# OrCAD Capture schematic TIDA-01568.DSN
size B; title: TIDA-01568 Power Sequence Simulation; rev: 1.0; note: TI Design: TIDA-01568; note: Synchronous Step Down Converter
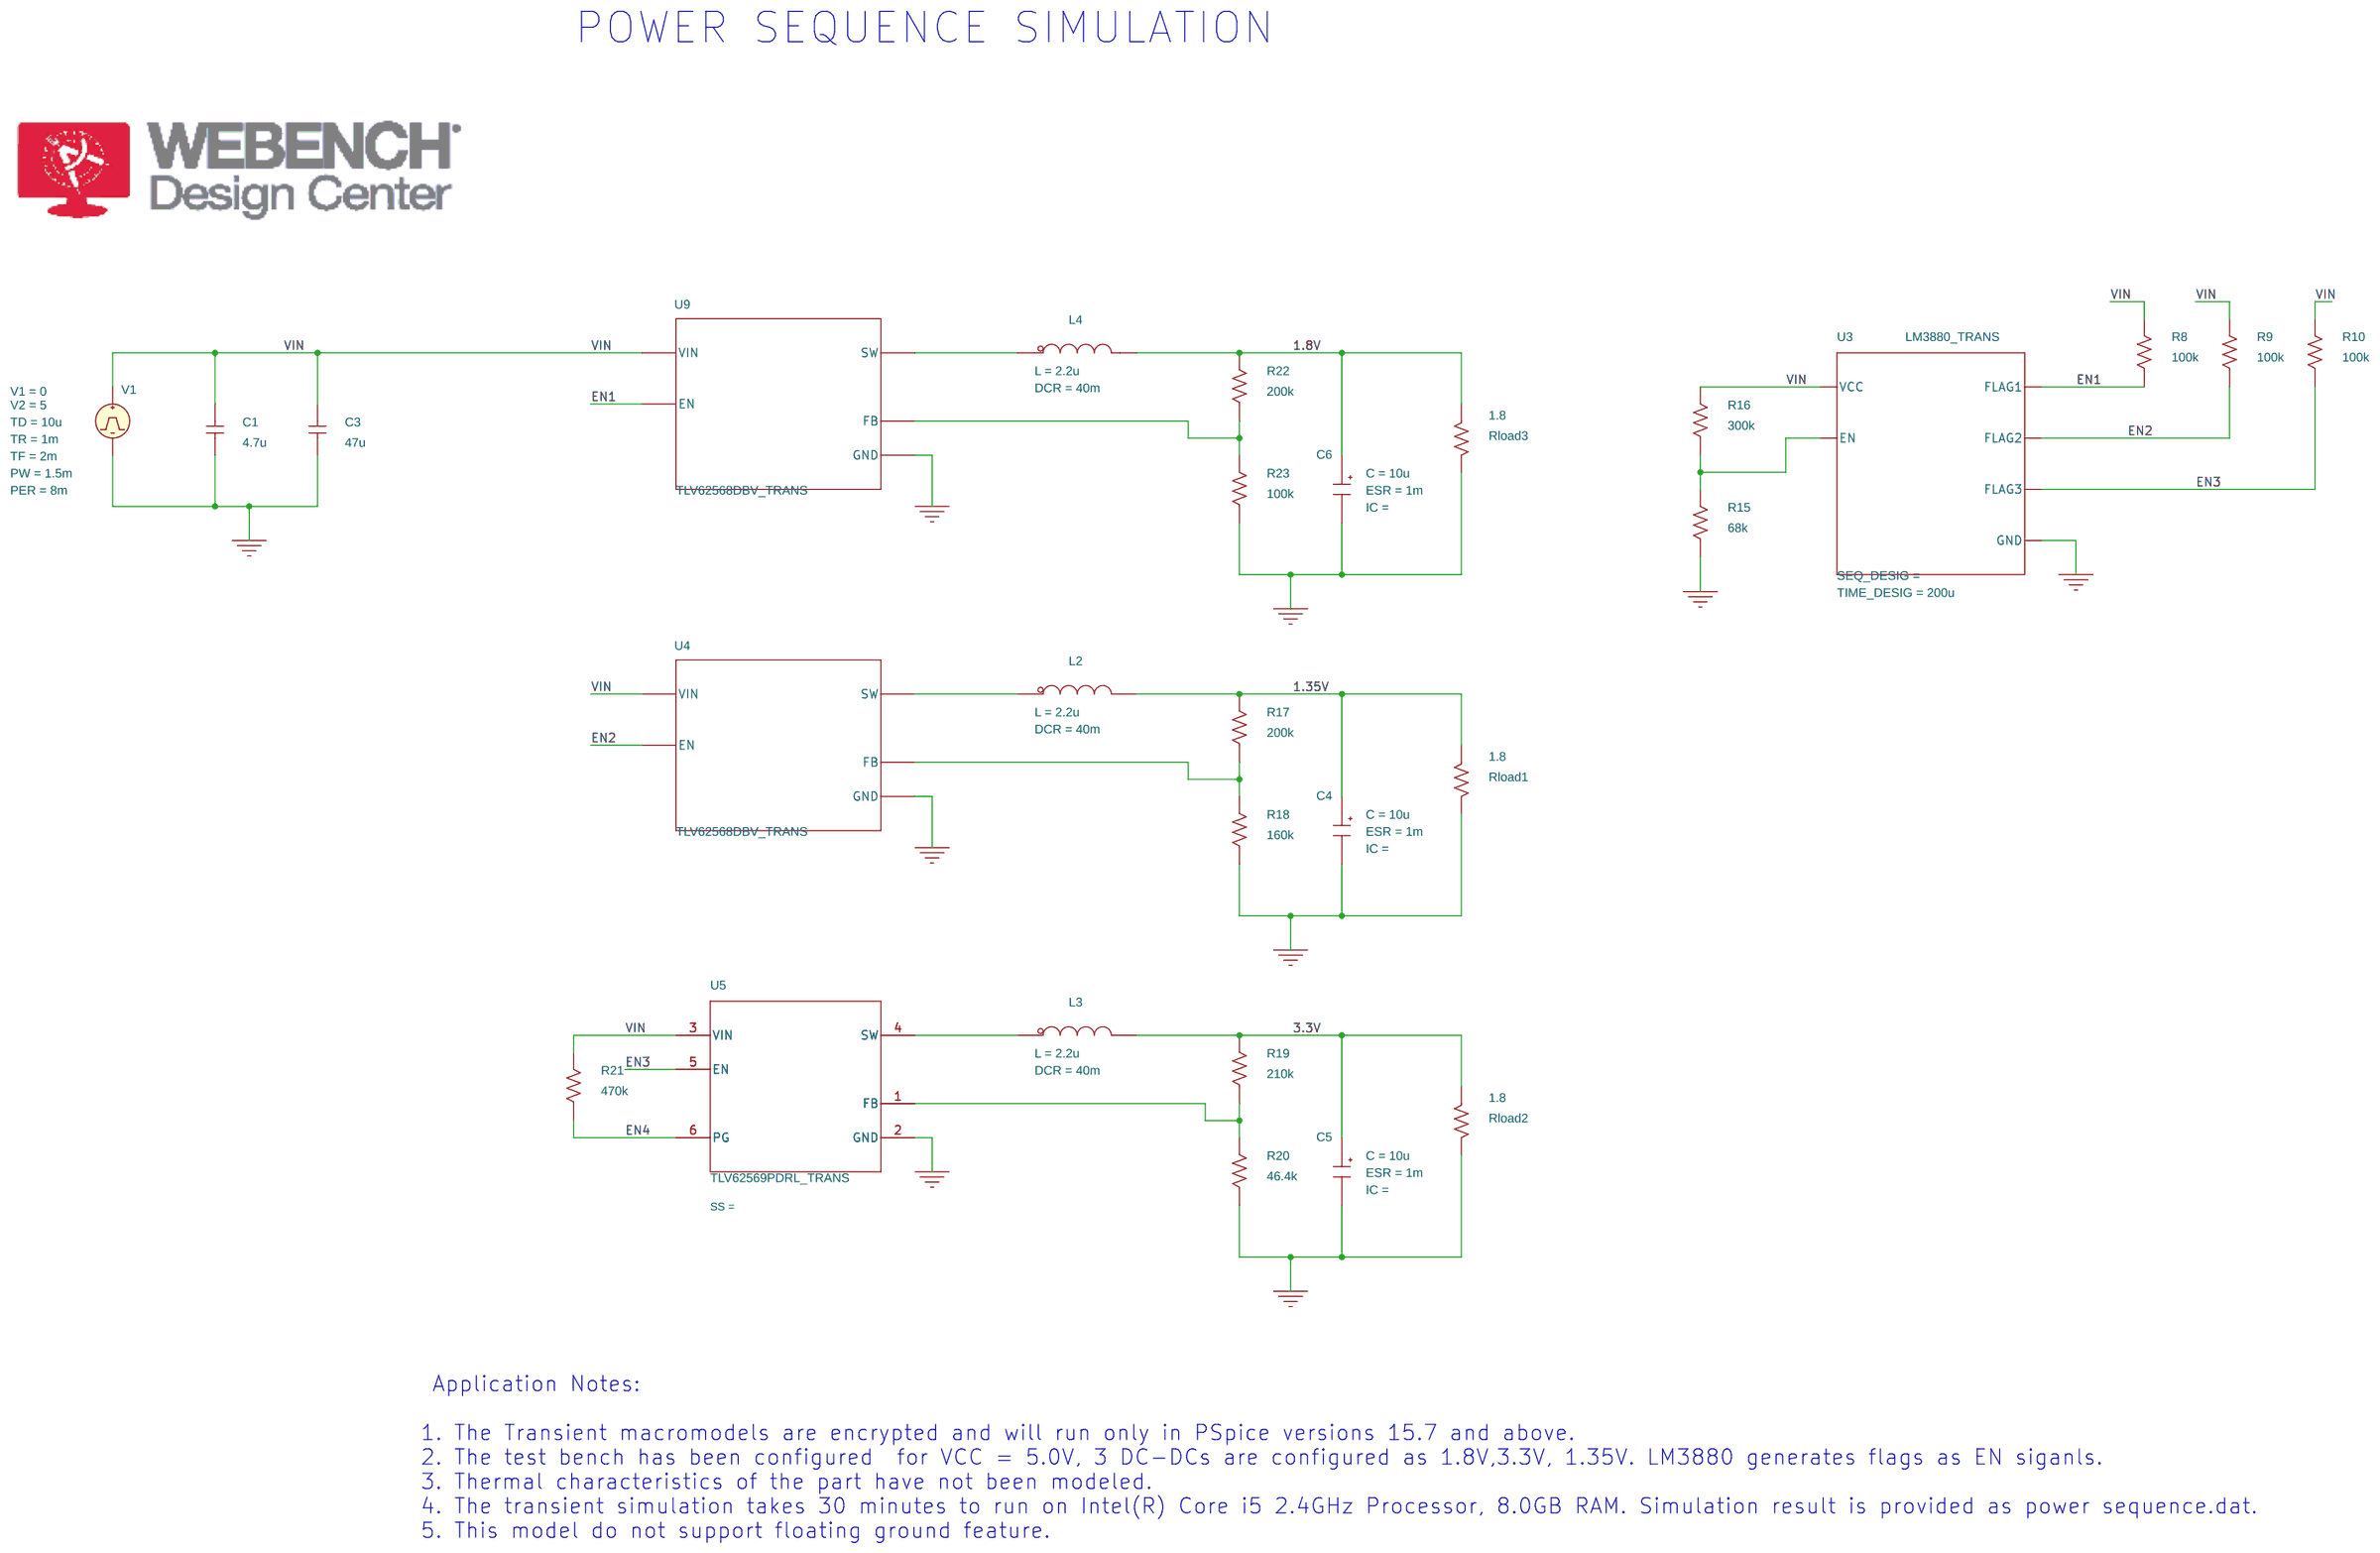
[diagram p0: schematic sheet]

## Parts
C1  4.7u  [RAD/CK05]
C3  47u  [RAD/CK05]
C4  CESR
C5  CESR
C6  CESR
L2  LDCR
L3  LDCR
L4  LDCR
R8  100k  [AX/RC05]
R9  100k  [AX/RC05]
R10  100k  [AX/RC05]
R15  68k  [AX/RC05]
R16  300k  [AX/RC05]
R17  200k  [AX/RC05]
R18  160k  [AX/RC05]
R19  210k  [AX/RC05]
R20  46.4k  [AX/RC05]
R21  470k  [AX/RC05]
R22  200k  [AX/RC05]
R23  100k  [AX/RC05]
Rload1  1.8  [AX/RC05]
Rload2  1.8  [AX/RC05]
Rload3  1.8  [AX/RC05]
U3  LM3880_TRANS
U4  TLV62568DBV_TRANS
U5  TLV62569PDRL_TRANS  [DRL0006A]
U9  TLV62568DBV_TRANS
V1  VPULSE

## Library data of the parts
C1 C3 = C
C4-C6 = CESR_0: C: 10u; ESR: 1m; PSpiceTemplate: X^@REFDES %IN %OUT @MODEL PARAMS:  ?C|C=@C||C=100u|  ?ESR|ESR=@ESR||ESR=0.01| ?X|X=@X||X=2|  ?IC|IC=@IC||IC=2|; X: 1
L2-L4 = LDCR_1: DCR: 40m; L: 2.2u; PSpiceTemplate: X^@REFDES %IN %OUT @MODEL PARAMS:  ?L|L=@L||L=1u|  ?DCR|DCR=@DCR||DCR=0.01|
R8-R10 R15-R23 Rload1-Rload3 = R
U3 = LM3880_TRANS: TIME_DESIG: 200u
U4 = TLV62568_TRANS_1
U5 = TLV62569PDRL_TRANS: PSpiceTemplate: X^@REFDES %EN %FB %GND %PG %SW %VIN @MODEL PARAMS: ?SS|SS=@SS||SS|
U9 = TLV62568_TRANS
V1 = VPULSE: PER: 8m; PW: 1.5m; TD: 10u; TF: 2m; TR: 1m; V1: 0; V2: 5

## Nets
1.8V: C6.1(IN) L4.3(OUT) R22.2 Rload3.1
1.35V: C4.1(IN) L2.3(OUT) R17.2 Rload1.1
3.3V: C5.1(IN) L3.3(OUT) R19.2 Rload2.1
VIN: C1.2 C3.2 R8.2 R9.2 R10.2 R16.2 R21.2 U3.VCC U4.VIN U5.3(VIN) U9.VIN V1.1(+)
0: C1.1 C3.1 C4.2(OUT) C5.2(OUT) C6.2(OUT) R15.1 R18.1 R20.1 R23.1 Rload1.2 Rload2.2 Rload3.2 U3.GND U4.GND U5.2(GND) U9.GND V1.2(-)
EN1: R8.1 U3.FLAG1 U9.EN
EN2: R9.1 U3.FLAG2 U4.EN
EN3: R10.1 U3.FLAG3 U5.5(EN)
EN4: R21.1 U5.6(PG)
N16783178: R17.1 R18.2 U4.FB
N16783401: L2.1(IN) U4.SW
N16784571: L3.1(IN) U5.4(SW)
N16784602: R19.1 R20.2 U5.1(FB)
N16786231: R15.2 R16.1 U3.EN
N16786518: L4.1(IN) U9.SW
N16786549: R22.1 R23.2 U9.FB

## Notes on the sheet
- POWER SEQUENCE SIMULATION
- Application Notes:
  1. The Transient macromodels are encrypted and will run only in PSpice versions 15.7 and above.
  2. The test bench has been configured  for VCC = 5.0V, 3 DC-DCs are configured as 1.8V,3.3V, 1.35V. LM3880 generates flags as EN siganls.
  3. Thermal characteristics of the part have not been modeled.
  4. The transient simulation takes 30 minutes to run on Intel(R) Core i5 2.4GHz Processor, 8.0GB RAM. Simulation result is provided as power sequence.dat.
  5. This model do not support floating ground feature.
